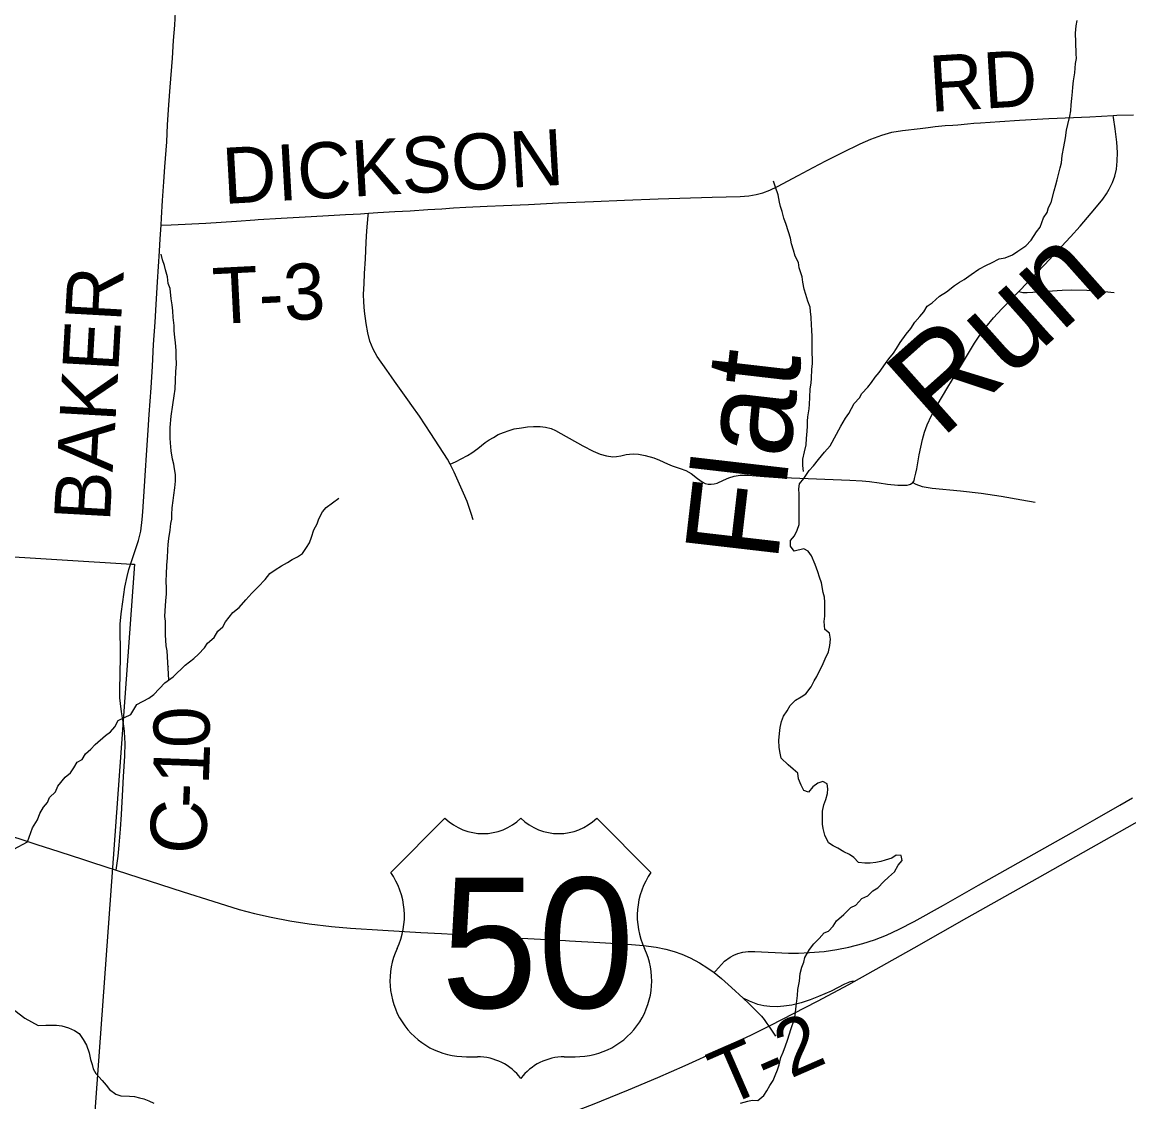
# Model space of a CAD drawing. Extents: x -8.2 to 34, y 0 to 22.
# Drawn here: x 7.291 to 8.412, y 15.949 to 17.043 of the extents above; entities that cross this region are included whole.
import ezdxf

# ---------------------------------------------------------------- set-up
doc = ezdxf.new("R2010")
doc.units = 0
for name, color, linetype in [('GM_X_Corporation', 7, 'Continuous'), ('GM_X_County_Road', 7, 'Continuous'), ('GM_X_County_Road_Text', 7, 'Continuous'), ('GM_X_Interchange_Ramps', 7, 'Continuous'), ('GM_X_Minor_River', 7, 'Continuous'), ('GM_X_Minor_River_Text', 7, 'Continuous'), ('GM_X_State_Route', 7, 'Continuous'), ('GM_X_Township_Road', 7, 'Continuous'), ('GM_X_Township_Road_Text', 7, 'Continuous'), ('GM_X_US_Location', 7, 'Continuous'), ('GM_X_US_Route', 7, 'Continuous'), ('GM_X_US_Shield', 7, 'Continuous')]:
    doc.layers.add(name, color=color, linetype=linetype)

msp = doc.modelspace()

# ---------------------------------------------------------------- linework, layer by layer
at = {"layer": 'GM_X_Corporation'}
msp.add_lwpolyline([(6.3752, 16.558), (7.4018, 16.494), (7.4044, 16.4939), (7.3299, 15.4643), (6.2993, 15.5265)], close=True, dxfattribs=at)
at = {"layer": 'GM_X_County_Road'}
for points in [[(7.3859, 16.1842), (7.3865, 16.1888), (7.3879, 16.1982), (7.3891, 16.2092), (7.3904, 16.2256), (7.3912, 16.2405), (7.3926, 16.2659), (7.3934, 16.2789), (7.3946, 16.2994), (7.3949, 16.3131), (7.3948, 16.3177), (7.3944, 16.3244), (7.3937, 16.3304), (7.3913, 16.3443), (7.3902, 16.3528), (7.3898, 16.3587), (7.3897, 16.3668), (7.3902, 16.3998), (7.3901, 16.4332), (7.3909, 16.4436), (7.3926, 16.4559), (7.3936, 16.4632), (7.3948, 16.4708), (7.397, 16.4816), (7.3987, 16.4885), (7.4034, 16.5027), (7.4085, 16.5179), (7.4109, 16.5274), (7.4122, 16.5393), (7.4129, 16.5469), (7.4147, 16.5729), (7.4157, 16.5889), (7.4165, 16.6046), (7.4182, 16.6299), (7.4193, 16.6458), (7.4214, 16.6727), (7.4226, 16.6945), (7.4237, 16.7167), (7.4253, 16.7393), (7.4265, 16.757), (7.4278, 16.7802), (7.4297, 16.811), (7.4305, 16.8237), (7.4314, 16.8375), (7.4318, 16.8449), (7.4328, 16.8624), (7.4341, 16.8814), (7.4352, 16.8967), (7.4371, 16.9218), (7.438, 16.939), (7.4394, 16.9595), (7.4407, 16.9774), (7.4429, 17.0067), (7.4441, 17.0245), (7.4453, 17.04), (7.4465, 17.0604)], [(8.0885, 16.1006), (8.1034, 16.1018), (8.1164, 16.1036), (8.1286, 16.1061), (8.1425, 16.1097), (8.1543, 16.1135), (8.1665, 16.1183), (8.1796, 16.1243), (8.1945, 16.1319), (8.2243, 16.1487), (8.26, 16.1689), (8.3324, 16.2098), (8.3541, 16.2219), (8.3779, 16.2354), (8.4031, 16.25), (8.4161, 16.2572)], [(7.9921, 16.0802), (7.9934, 16.0817), (8.0026, 16.092), (8.0081, 16.0959), (8.0118, 16.0979), (8.0158, 16.0995), (8.021, 16.1009), (8.0264, 16.1017), (8.0332, 16.1018), (8.0673, 16.1001), (8.0773, 16.1), (8.0885, 16.1006)]]:
    msp.add_lwpolyline(points, dxfattribs=at)
at = {"layer": 'GM_X_Interchange_Ramps'}
msp.add_lwpolyline([(8.1337, 16.0712), (8.1316, 16.0712), (8.1302, 16.0709), (8.1288, 16.0705), (8.1274, 16.07), (8.1242, 16.0684), (8.1107, 16.0615), (8.0977, 16.0561), (8.0891, 16.0526), (8.0803, 16.0497), (8.0706, 16.0474), (8.0627, 16.0461), (8.0559, 16.0456), (8.0484, 16.0458), (8.0423, 16.0465), (8.0362, 16.0481), (8.0278, 16.0512), (8.0213, 16.0544)], dxfattribs=at)
at = {"layer": 'GM_X_Minor_River'}
for points in [[(8.1042, 16.4557), (8.1038, 16.4607), (8.1023, 16.4652), (8.1009, 16.4751), (8.0986, 16.4809), (8.0971, 16.4862), (8.0945, 16.4938), (8.0907, 16.5026), (8.0874, 16.5072), (8.0828, 16.5095), (8.0729, 16.5072), (8.0695, 16.5122), (8.0692, 16.5179), (8.0734, 16.5228), (8.0761, 16.5285), (8.078, 16.5342), (8.0781, 16.5563), (8.0782, 16.5651), (8.0778, 16.5704), (8.0786, 16.5753), (8.0828, 16.581), (8.0882, 16.589), (8.0928, 16.5935), (8.0978, 16.6), (8.1039, 16.6075), (8.1096, 16.614), (8.1204, 16.6337), (8.125, 16.6421), (8.1285, 16.6466), (8.1338, 16.6569), (8.1392, 16.6625), (8.1415, 16.6671), (8.1476, 16.6732), (8.1515, 16.6781), (8.1553, 16.6834), (8.1591, 16.6883), (8.1656, 16.6974), (8.1691, 16.702), (8.1737, 16.7077), (8.1767, 16.7126), (8.1806, 16.7187), (8.1867, 16.727), (8.1913, 16.7327), (8.1955, 16.7391), (8.2005, 16.7448), (8.2043, 16.7497), (8.2078, 16.7554), (8.2128, 16.7588), (8.2204, 16.7656), (8.2273, 16.7698), (8.2357, 16.7762), (8.2406, 16.7796), (8.2452, 16.7826), (8.2525, 16.7875), (8.2601, 16.7928), (8.2681, 16.797), (8.2731, 16.7992), (8.2807, 16.8034), (8.2868, 16.8045), (8.2944, 16.8075), (8.2998, 16.8113), (8.3078, 16.8166), (8.3131, 16.8222), (8.3185, 16.8306), (8.3223, 16.8355), (8.3258, 16.845), (8.3296, 16.8503), (8.3308, 16.8553), (8.3335, 16.8606), (8.3366, 16.8724), (8.3382, 16.8784), (8.3397, 16.8834), (8.3428, 16.8955), (8.344, 16.9005), (8.3448, 16.9081), (8.3464, 16.9168), (8.3479, 16.926), (8.3491, 16.9336), (8.3503, 16.9396), (8.3523, 16.948), (8.3534, 16.9533), (8.3538, 16.9594), (8.3543, 16.9659), (8.3551, 16.9727), (8.3555, 16.9773), (8.3563, 16.9838), (8.3574, 16.9917), (8.3583, 17.0013), (8.3591, 17.0062), (8.3587, 17.0111), (8.3584, 17.0229), (8.3581, 17.0321), (8.3589, 17.0393), (8.3597, 17.045)], [(8.0825, 16.5879), (8.0818, 16.594), (8.0818, 16.6004), (8.0834, 16.6077), (8.0853, 16.6149), (8.0857, 16.6213), (8.0861, 16.6289), (8.0866, 16.6339), (8.0866, 16.6388), (8.087, 16.6434), (8.0882, 16.6514), (8.0886, 16.6563), (8.089, 16.6628), (8.0894, 16.6716), (8.0902, 16.6773), (8.0906, 16.6826), (8.0911, 16.6913), (8.0915, 16.6974), (8.0915, 16.7027), (8.0912, 16.7073), (8.0913, 16.7244), (8.0909, 16.7313), (8.0906, 16.7362), (8.0902, 16.7442), (8.0895, 16.7499), (8.0891, 16.7545), (8.0869, 16.7606), (8.085, 16.7671), (8.0832, 16.7728), (8.0817, 16.7797), (8.0813, 16.785), (8.078, 16.7941), (8.0776, 16.7995), (8.0742, 16.806), (8.0724, 16.8121), (8.0705, 16.8185), (8.0694, 16.8243), (8.0649, 16.838), (8.0627, 16.8445), (8.0608, 16.8513), (8.0593, 16.8563), (8.0582, 16.8608), (8.0567, 16.8681), (8.0541, 16.8761), (8.0522, 16.8822)], [(7.4392, 16.3768), (7.4376, 16.4062), (7.4365, 16.4112), (7.4362, 16.4169), (7.4358, 16.4222), (7.4359, 16.4363), (7.4352, 16.4409), (7.4356, 16.4469), (7.4364, 16.4568), (7.4368, 16.4641), (7.4369, 16.4694), (7.4365, 16.477), (7.4369, 16.4838), (7.4374, 16.493), (7.4378, 16.5006), (7.4382, 16.5086), (7.4386, 16.5139), (7.4394, 16.52), (7.4406, 16.5284), (7.4414, 16.5352), (7.4422, 16.5398), (7.4422, 16.5443), (7.4426, 16.5512), (7.4438, 16.5584), (7.4442, 16.5641), (7.4454, 16.5713), (7.4462, 16.5782), (7.4459, 16.585), (7.4451, 16.5907), (7.4444, 16.5953), (7.4429, 16.6003), (7.4418, 16.609), (7.4411, 16.617), (7.4408, 16.6216), (7.4408, 16.6326), (7.4416, 16.644), (7.4432, 16.6554), (7.4448, 16.6646), (7.4456, 16.6714), (7.446, 16.6805), (7.4465, 16.6893), (7.4469, 16.6965), (7.4466, 16.7045), (7.4466, 16.7106), (7.4459, 16.7182), (7.4455, 16.7239), (7.4448, 16.7304), (7.4448, 16.7357), (7.4437, 16.7441), (7.4434, 16.7506), (7.4427, 16.7567), (7.4416, 16.7628), (7.4405, 16.7734), (7.4386, 16.7784), (7.4379, 16.7852), (7.436, 16.7921), (7.4349, 16.7967), (7.433, 16.8024), (7.4316, 16.8081)], [(7.2961, 16.2129), (7.3012, 16.2269), (7.3062, 16.2349), (7.3085, 16.2413), (7.3124, 16.2478), (7.3162, 16.2527), (7.3185, 16.2576), (7.3243, 16.2633), (7.3269, 16.269), (7.3342, 16.2781), (7.3396, 16.2827), (7.343, 16.2876), (7.3465, 16.2933), (7.3514, 16.2963), (7.3549, 16.302), (7.3603, 16.3065), (7.3645, 16.3115), (7.3752, 16.3205), (7.3801, 16.3243), (7.3847, 16.3292), (7.3878, 16.3357), (7.4008, 16.3417), (7.4069, 16.352), (7.4191, 16.3584), (7.4241, 16.3621), (7.4352, 16.3739), (7.4436, 16.3799), (7.4558, 16.3917), (7.4646, 16.3985), (7.4692, 16.403), (7.4753, 16.4094), (7.4784, 16.414), (7.4852, 16.4197), (7.4891, 16.4261), (7.4941, 16.4307), (7.4967, 16.4356), (7.504, 16.4451), (7.5105, 16.45), (7.5174, 16.4579), (7.5235, 16.4648), (7.5297, 16.4712), (7.5369, 16.4784), (7.5415, 16.4845), (7.5472, 16.4882), (7.5534, 16.4924), (7.5595, 16.4958), (7.5644, 16.4988), (7.5698, 16.5014), (7.5747, 16.5048), (7.5789, 16.5109), (7.582, 16.5158), (7.5839, 16.5215), (7.5863, 16.5288), (7.5897, 16.5348), (7.5913, 16.5401), (7.5951, 16.547), (7.5986, 16.5515), (7.6051, 16.5561), (7.6115, 16.561)], [(8.0485, 15.9659), (8.0516, 15.9708), (8.0539, 15.9761), (8.0562, 15.9818), (8.0578, 15.9868), (8.0597, 15.9944), (8.062, 15.9997), (8.0643, 16.0061), (8.0663, 16.0118), (8.0701, 16.0236), (8.0729, 16.0323), (8.074, 16.0373), (8.0752, 16.0464), (8.0756, 16.0517), (8.0764, 16.0571), (8.0768, 16.0631), (8.0784, 16.0715), (8.0792, 16.0795), (8.0808, 16.0856), (8.0827, 16.0909), (8.0839, 16.0955), (8.0885, 16.1038), (8.0931, 16.1095), (8.0984, 16.1148), (8.1034, 16.1205), (8.108, 16.1223), (8.1126, 16.1273), (8.116, 16.1326), (8.1233, 16.139), (8.1305, 16.1462), (8.1355, 16.1485), (8.1416, 16.1553), (8.1477, 16.1579), (8.1527, 16.1632), (8.1577, 16.1662), (8.1638, 16.1727), (8.1688, 16.1768), (8.1749, 16.1825), (8.1783, 16.189), (8.1825, 16.1939), (8.1814, 16.1988), (8.1765, 16.1992), (8.1719, 16.1962), (8.1654, 16.194), (8.1609, 16.1929), (8.1559, 16.1917), (8.1502, 16.191), (8.1445, 16.191), (8.1384, 16.1918), (8.1335, 16.1968), (8.129, 16.1999), (8.1233, 16.2026), (8.1172, 16.2064), (8.1127, 16.2087), (8.1077, 16.2118), (8.104, 16.2194), (8.1025, 16.2263), (8.1018, 16.2308), (8.1018, 16.2438), (8.103, 16.2502), (8.1053, 16.2555), (8.1069, 16.2616), (8.1073, 16.2666), (8.1065, 16.2715), (8.102, 16.2738), (8.097, 16.2723), (8.0921, 16.2686), (8.0875, 16.2632), (8.0829, 16.2648), (8.0803, 16.2701), (8.0773, 16.2766), (8.0766, 16.2823), (8.072, 16.2862), (8.0671, 16.2908), (8.0599, 16.2976), (8.0584, 16.3041), (8.0577, 16.3087), (8.0574, 16.3155), (8.0582, 16.3224), (8.059, 16.3285), (8.0601, 16.3345), (8.0624, 16.3402), (8.0659, 16.3456), (8.069, 16.3509), (8.0743, 16.3562), (8.08, 16.3596), (8.085, 16.3626), (8.0904, 16.3698), (8.0934, 16.3759), (8.0961, 16.3804), (8.0984, 16.3853), (8.1015, 16.391), (8.1046, 16.3983), (8.1077, 16.4051), (8.1092, 16.4115), (8.11, 16.418), (8.1089, 16.4241), (8.104, 16.4279), (8.1033, 16.4359), (8.1041, 16.4413), (8.1042, 16.4557)], [(7.4387, 16.3906), (7.4387, 16.3905)], [(7.2191, 16.1137), (7.2214, 16.119), (7.223, 16.1243), (7.2257, 16.1303), (7.2265, 16.136), (7.2269, 16.1413), (7.2327, 16.1462), (7.2403, 16.1541), (7.2438, 16.1598), (7.2504, 16.1673), (7.2534, 16.1726), (7.2577, 16.1779), (7.2611, 16.1832), (7.2669, 16.1888), (7.2715, 16.1944), (7.2776, 16.2001), (7.2823, 16.2054), (7.2961, 16.2129)], [(7.2503, 16.069), (7.2584, 16.0612), (7.2637, 16.057), (7.2705, 16.0504), (7.2762, 16.0477), (7.2833, 16.0419), (7.2935, 16.0342), (7.3069, 16.0267)], [(7.3069, 16.0267), (7.3145, 16.0271), (7.3256, 16.027), (7.3309, 16.0262), (7.3377, 16.0243), (7.3438, 16.0216), (7.3483, 16.0185), (7.3525, 16.0124), (7.3559, 16.0067), (7.3585, 15.9991), (7.36, 15.9922), (7.3615, 15.9873), (7.3626, 15.9827), (7.3652, 15.9781), (7.3716, 15.9708), (7.3758, 15.9663), (7.3792, 15.9617), (7.3856, 15.9571), (7.3906, 15.9555), (7.3993, 15.9551), (7.4046, 15.9547), (7.4096, 15.9535), (7.4141, 15.9524), (7.4191, 15.9504), (7.424, 15.9481)], [(8.0188, 15.9481), (8.026, 15.95), (8.0306, 15.9511), (8.0363, 15.9507), (8.0424, 15.9556), (8.0454, 15.9606), (8.0485, 15.9659)]]:
    msp.add_lwpolyline(points, dxfattribs=at)
at = {"layer": 'GM_X_State_Route'}
for points in [[(8.0093, 16.0077), (8.029, 16.017), (8.0473, 16.0261)], [(7.2201, 15.7306), (7.2917, 15.7539), (7.3441, 15.7709), (7.3883, 15.7856), (7.4441, 15.8039), (7.5008, 15.8224), (7.5616, 15.8421), (7.6557, 15.8731), (7.714, 15.8919), (7.7468, 15.9025), (7.8086, 15.9239), (7.8367, 15.9344), (7.8688, 15.9467), (7.9053, 15.9614), (7.935, 15.9739), (7.9627, 15.9861), (7.9967, 16.0017), (8.0093, 16.0077)]]:
    msp.add_lwpolyline(points, dxfattribs=at)
at = {"layer": 'GM_X_Township_Road'}
for points in [[(7.4314, 16.8375), (7.4415, 16.8379), (7.4769, 16.8396), (7.5079, 16.8416), (7.5264, 16.8428), (7.53, 16.8431), (7.5531, 16.8445), (7.5773, 16.846), (7.5953, 16.847), (7.6182, 16.8482), (7.6262, 16.8487), (7.6337, 16.8491), (7.6415, 16.8496), (7.651, 16.8503), (7.6684, 16.8513), (7.6839, 16.8521), (7.7018, 16.8532), (7.7161, 16.8541), (7.7278, 16.8549), (7.7402, 16.8556), (7.7618, 16.8567), (7.7785, 16.8575), (7.8039, 16.8585), (7.8343, 16.8601), (7.8696, 16.8615), (7.9012, 16.8628), (7.9353, 16.864), (7.9898, 16.8659), (8.0184, 16.8664), (8.0272, 16.8671), (8.0346, 16.8684), (8.0413, 16.8702), (8.0483, 16.8728), (8.0563, 16.8765), (8.077, 16.8878), (8.0924, 16.896), (8.1051, 16.9025), (8.1222, 16.9112), (8.1401, 16.9198), (8.1509, 16.9246), (8.1618, 16.9287), (8.1719, 16.9316), (8.1828, 16.9335), (8.2007, 16.9355), (8.2087, 16.9363), (8.2161, 16.9373), (8.226, 16.9383), (8.234, 16.9389), (8.2389, 16.9393), (8.2488, 16.9401), (8.255, 16.9407), (8.2618, 16.9412), (8.2816, 16.9425), (8.3014, 16.9438), (8.3312, 16.9455), (8.3728, 16.9473), (8.3963, 16.9486), (8.4001, 16.9488), (8.4168, 16.9494)], [(7.7245, 16.5954), (7.7268, 16.5964), (7.7304, 16.5982), (7.7354, 16.6008), (7.742, 16.6042), (7.7464, 16.6068), (7.7525, 16.6111), (7.7599, 16.6173), (7.764, 16.6201), (7.7683, 16.6225), (7.7732, 16.6253), (7.7783, 16.6275), (7.7841, 16.6295), (7.7894, 16.6311), (7.7967, 16.6323), (7.8029, 16.6331), (7.8089, 16.6336), (7.8155, 16.6334), (7.8212, 16.6328), (7.8267, 16.6315), (7.8311, 16.6295), (7.8365, 16.6265), (7.8589, 16.614), (7.8694, 16.6084), (7.8763, 16.6055), (7.8829, 16.6037), (7.8892, 16.6028), (7.8931, 16.6032), (7.8973, 16.6039), (7.9029, 16.6052), (7.9061, 16.6056), (7.9104, 16.6057), (7.9152, 16.6055), (7.9219, 16.6043), (7.9307, 16.6018), (7.9367, 16.5995), (7.9447, 16.5956), (7.9493, 16.5938), (7.9516, 16.593), (7.9575, 16.591), (7.9633, 16.5888), (7.9688, 16.5859), (7.9751, 16.5809), (7.9797, 16.5776), (7.983, 16.5759), (7.986, 16.5752), (7.989, 16.575), (7.9921, 16.5754), (7.9951, 16.5762), (8.0013, 16.5791), (8.007, 16.5816), (8.0123, 16.5833), (8.0184, 16.5841), (8.0265, 16.5842), (8.0428, 16.5827), (8.0569, 16.5818), (8.0704, 16.5814), (8.104, 16.5801), (8.1295, 16.5793), (8.1418, 16.5784), (8.1493, 16.5778), (8.1591, 16.5764), (8.1677, 16.5752), (8.1781, 16.5742), (8.1839, 16.5741), (8.1877, 16.5742), (8.1898, 16.5746), (8.191, 16.5751), (8.1934, 16.5769), (8.1945, 16.5786), (8.1951, 16.5808), (8.1963, 16.5864), (8.1972, 16.5905), (8.1997, 16.6047), (8.2031, 16.6205), (8.205, 16.6277), (8.2077, 16.6353), (8.2121, 16.6448), (8.2179, 16.6552), (8.2288, 16.6732), (8.2436, 16.6977), (8.2557, 16.7179), (8.262, 16.7272), (8.2672, 16.7342), (8.2752, 16.7437), (8.2835, 16.7528), (8.3009, 16.7702), (8.327, 16.7977), (8.344, 16.816), (8.3532, 16.8258), (8.3628, 16.8364), (8.3779, 16.854), (8.3858, 16.8639), (8.3895, 16.8692), (8.3924, 16.8739), (8.3957, 16.8806), (8.398, 16.887), (8.3997, 16.8943), (8.4005, 16.9023), (8.4007, 16.911), (8.4, 16.9215), (8.3984, 16.935), (8.3966, 16.9466), (8.3963, 16.9486)], [(7.7477, 16.5389), (7.7458, 16.5453), (7.744, 16.5505), (7.7415, 16.5576), (7.7378, 16.5661), (7.7286, 16.5872), (7.7245, 16.5954), (7.7217, 16.6004), (7.7048, 16.6264), (7.6933, 16.6441), (7.6857, 16.6547), (7.6814, 16.6607), (7.6681, 16.6794), (7.6649, 16.684), (7.6603, 16.6906), (7.6505, 16.7043), (7.6463, 16.7118), (7.6431, 16.7199), (7.6409, 16.7283), (7.6392, 16.7379), (7.6376, 16.7502), (7.6369, 16.7594), (7.6367, 16.7675), (7.6372, 16.7781), (7.6377, 16.7886), (7.6385, 16.8035), (7.6393, 16.8202), (7.6401, 16.8319), (7.6413, 16.8474), (7.6415, 16.8496)], [(8.3009, 16.7702), (8.3048, 16.7693), (8.3093, 16.7692), (8.3149, 16.7696), (8.3447, 16.7717), (8.354, 16.772), (8.3695, 16.7716), (8.3876, 16.7704), (8.3975, 16.7693)], [(8.1934, 16.5769), (8.1957, 16.5755), (8.198, 16.5743), (8.2001, 16.5736), (8.2029, 16.5728), (8.213, 16.5712), (8.2417, 16.5685), (8.2627, 16.5661), (8.283, 16.5631), (8.3038, 16.5592), (8.3174, 16.5567)]]:
    msp.add_lwpolyline(points, dxfattribs=at)
at = {"layer": 'GM_X_US_Route'}
for points in [[(8.0473, 16.0261), (8.0488, 16.0268), (8.0968, 16.0513), (8.1286, 16.0683), (8.1337, 16.0712), (8.1946, 16.1055), (8.2482, 16.1356), (8.3196, 16.1759), (8.4337, 16.2405), (8.491, 16.2729), (8.544, 16.3028), (8.6939, 16.3874), (8.8528, 16.4774), (8.9, 16.504)], [(7.2652, 16.2231), (7.3054, 16.21), (7.3278, 16.2029), (7.3414, 16.1985), (7.3509, 16.1955), (7.3621, 16.1919), (7.3859, 16.1842), (7.4537, 16.1621), (7.4838, 16.1525), (7.5105, 16.1443), (7.526, 16.1401), (7.5429, 16.1363), (7.5618, 16.1327), (7.5814, 16.1297), (7.6041, 16.1268), (7.6233, 16.1252), (7.6561, 16.1232), (7.6946, 16.121), (7.7157, 16.1198), (7.7392, 16.1185), (7.7621, 16.117), (7.803, 16.1147), (7.8414, 16.1127), (7.8454, 16.1124)], [(7.8454, 16.1124), (7.8761, 16.1106), (7.904, 16.1091), (7.9202, 16.1077), (7.9331, 16.106), (7.943, 16.1041), (7.9514, 16.1017), (7.9591, 16.0989), (7.9676, 16.0951), (7.977, 16.0901), (7.9855, 16.0849), (7.9921, 16.0802), (7.9995, 16.0743), (8.0096, 16.0651), (8.0213, 16.0544), (8.0271, 16.0488), (8.0398, 16.0361), (8.0426, 16.0328), (8.0455, 16.0288), (8.0473, 16.0261), (8.0501, 16.0219), (8.0543, 16.0158)]]:
    msp.add_lwpolyline(points, dxfattribs=at)
at = {"layer": 'GM_X_US_Shield'}
for p, q in [((7.7191, 16.2367), (7.6642, 16.1818)), ((7.9279, 16.1818), (7.873, 16.2367)), ((7.7411, 15.995), (7.7521, 15.995)), ((7.84, 15.995), (7.851, 15.995))]:
    msp.add_line(p, q, dxfattribs=at)
for centre, radius, start, end in [((7.7576, 16.276), 0.0549, 225.573, 314.427), ((7.8345, 16.276), 0.0549, 225.573, 314.427), ((7.6012, 16.1377), 0.0769, 334.5471, 35.0009), ((7.9909, 16.1377), 0.0769, 144.9991, 205.4529), ((7.7403, 16.0719), 0.0769, 154.8319, 270.6383), ((7.8518, 16.0719), 0.0769, 269.3617, 25.1681), ((7.7521, 15.9401), 0.0549, 36.8699, 90), ((7.84, 15.9401), 0.0549, 90, 143.1301)]:
    msp.add_arc(centre, radius, start, end, dxfattribs=at)

# ---------------------------------------------------------------- texts
at = {"layer": 'GM_X_County_Road_Text'}
for s, height, rotation, p in [('BAKER', 0.05682, 86.7968, (7.3795, 16.5364)), ('0', 0.0568, 90.9505, (7.481, 16.3082)), ('1', 0.0568, 87.8678, (7.4797, 16.2699)), ('-', 0.0568, 87.3729, (7.4786, 16.246)), ('C', 0.0568, 87.2473, (7.4763, 16.1993))]:
    msp.add_text(s, height=height, rotation=rotation, dxfattribs=at).set_placement(p)
at = {"layer": 'GM_X_Minor_River_Text'}
for s, height, rotation, p in [('Run', 0.0947, 41.697, (8.222, 16.6203)), ('Flat', 0.09471, 83.4102, (8.056, 16.4949))]:
    msp.add_text(s, height=height, rotation=rotation, dxfattribs=at).set_placement(p)
at = {"layer": 'GM_X_Township_Road_Text'}
for s, rotation, p in [('RD', 3.4534, (8.2114, 16.9522)), ('DICKSON', 3.2393, (7.495, 16.8589)), ('T-3', 2.8627, (7.4851, 16.7372)), ('T-2', 23.572, (8.0037, 15.9441))]:
    msp.add_text(s, height=0.05682, rotation=rotation, dxfattribs=at).set_placement(p)
at = {"layer": 'GM_X_US_Location'}
for s in ['0', '/']:
    msp.add_text(s, height=0.000189, dxfattribs=at).set_placement((7.796, 16.1093))
msp.add_text('50', height=0.000189, rotation=0, dxfattribs=at).set_placement((7.7569, 16.0701))
at = {"layer": 'GM_X_US_Shield'}
msp.add_text('50', height=0.13184, dxfattribs=at).set_placement((7.7151, 16.0445))

doc.saveas('drawing.dxf')
